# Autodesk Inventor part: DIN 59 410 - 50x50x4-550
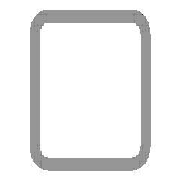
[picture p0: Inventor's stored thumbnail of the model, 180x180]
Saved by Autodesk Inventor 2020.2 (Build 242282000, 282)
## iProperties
Manager: www.cadconsulting.pl
Company: Fabian Stasiak CAD Consulting
Created: 2015-01
Part Number: DIN 59 410 - 50x50x4-550
Material: Stal, miękka
Description: Rurki stalowe o przekroju kwadratowym formowane na gorąco
Document SubType Name: Modellieren
Standard: DIN
Designer: F.Stasiak
Standards Organization: DIN
Language: pl-PL
Size Designation: 50x50x4
Categories: <MemberInstance><Categories><Category DisplayName="Kształtowniki konstrukcyjne" InternalName="089c4875-fa83-4c05-b084-43b9cc11f5ed" Mnemonic="GRDR"><CategoryPar
Stock Number: 50x50x4
Density: 7.85 g/cm^3
Appearance: Częściowo polerowana
Mass: 2999.78 g
Surface Area: 1924.59 cm^2
Volume: 382.138 cm^3
Catalog Web Link: www.expertbooks.pl
_CCFamilyMember: 40
_CCFamilyDisplayName: DIN 59410 (Kwadrat) - Rurki stalowe o przekroju kwadratowym formowane na gorąco
_FrameMemberDoc: Frame Member File
_Version: 15.0.0
_GetPNFromCC: 1
G_W: 50,000 mm
G_H: 50,000 mm
+68FBBC7B-E8AB-4C98-8F6E-119E676535F4+CUTDETAIL1: Wytnij
+F3E6DE4A-D29C-4A40-94F5-B8932DC674AB+CUTDETAIL2: Wytnij
G_L: 550,000 mm
IsCustomPart: 1
Author: F.Stasiak
Subject: Zbiór ćwiczeń. Autodesk Inventor 2020. Kurs Professional
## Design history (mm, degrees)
node "Płaszczyzna początkowa"
node "Płaszczyzna końcowa"
sketch "Szkic"
  geometry: L1 (-17, 25)-(17, 25); L2 (25, 17)-(25, -17); L3 (17, -25)-(-17, -25); L4 (-25, -17)-(-25, 17); L5 (-37.32, 0)-(37.32, 0) reference; L6 (0, -37.32)-(0, 37.32) reference; L7 (-17, 21)-(17, 21); L8 (21, 17)-(21, -17); L9 (17, -21)-(-17, -21); L10 (-21, -17)-(-21, 17); A1 r 8 centre (-17, 17) between (-17, 25) and (-25, 17); A2 r 8 centre (17, 17) between (25, 17) and (17, 25); A3 r 8 centre (17, -17) between (17, -25) and (25, -17); A4 r 8 centre (-17, -17) between (-25, -17) and (-17, -25); A5 r 4 centre (-17, 17) between (-17, 21) and (-21, 17); A6 r 4 centre (17, 17) between (21, 17) and (17, 21); A7 r 4 centre (17, -17) between (17, -21) and (21, -17); A8 r 4 centre (-17, -17) between (-21, -17) and (-17, -21); 3 further points
  constraints: 16 end point, 16 point on circle, 8 centre point, 8 tangent, 6 point on line, 4 parallel, 3 equal radius, 3 perpendicular, 1 horizontal, 7 other
  dimensions: "b" = 50 distance of point (-25, 25) point (25, 25); "msp_r" = 8 radius of A1 (= 2 x ParT); "d8" = 25 distance between parallel lines of L4 L6 (= d9); "d9" = 25 distance between parallel lines of L3 L5 (= 0.5 x b); "d10" = 4 distance between parallel lines of L3 L9 (= ParT)
extrude "Bryła" new body sketch "Szkic" taper "d4" = 0 deg; stored distance "NLG" = 10
node "Driven Length"
  sketch "Sketch2"
    geometry: L1 (0, 0)-(10, 0) reference
    constraints: 2 end point, 1 horizontal
  workplane "Work Plane3"
  sketch "Sketch3"
    geometry: L1 (-2, 25)-(12, 25) reference; L2 (-2, 575)-(12, 575) reference
    dimensions: "d14" = 550 distance between parallel lines of L1 L2 (derived)
node "Płaszczyzna konstrukcyjna4"
feature "Podział1"
node "Płaszczyzna konstrukcyjna5"
feature "Podział2"
body "Solid1"
other parameters: "ParT" = 4, "G_OFFSET_START" = -25 [user parameter; used in 1 equation term], "G_OFFSET_END" = -25 [user parameter; used in 1 equation term], "d11" = 25 (= -G_OFFSET_START), "d12" = 575 (= G_OFFSET_END + B_L), "G_L" = 550 (= d14) [user parameter], "d13" = 90 deg
